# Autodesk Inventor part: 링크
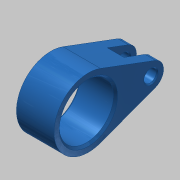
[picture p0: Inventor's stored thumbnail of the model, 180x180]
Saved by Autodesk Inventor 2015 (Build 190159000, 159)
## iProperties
Created: 2016-08
Part Number: 링크
Material: 강철, 탄소
Document SubType Name: Modeling
Designer: mduedu
Density: 7.87 g/cm^3
Appearance: 청록색
Author: mduedu
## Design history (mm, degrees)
sketch "스케치1"
  geometry: L1 (32.1, 5.62)-(5.775, 15.456); L2 (32.1, -5.62)-(5.775, -15.456); C1 r 13 at (0, 0); C2 r 3 at (30, 0); A1 r 16.5 centre (0, 0) between (5.775, 15.456) and (5.775, -15.456); A2 r 6 centre (30, 0) between (32.1, 5.62) and (32.1, -5.62); 1 further point
  constraints: 4 centre point, 4 end point, 4 point on circle, 4 tangent, 3 coincident, 1 horizontal alignment
  dimensions: "d0" = 33 diameter of A1; "d2" = 12 diameter of A2; "d3" = 30 distance of A2.centre point (0, 0); "d4" = 26 diameter of C1; "d5" = 6 diameter of C2
extrude "돌출1" new body sketch "스케치1" stored distance "d6" = 18; taper "d7" = 0 deg
sketch "스케치2"
  geometry: L1 (-9, 36)-(9, 36) reference; L2 (0, 0)-(0, 36); L3 (-4, 36)-(4, 36); L4 (4, 36)-(4, 22); L5 (4, 22)-(-4, 22); L6 (-4, 22)-(-4, 36)
  constraints: 10 end point, 2 midpoint, 2 parallel, 1 horizontal, 1 perpendicular, 1 point on line
  dimensions: "d8" = 8 distance between parallel lines of L4 L6; "d10" = 14 distance of L3.end L4.end
extrude "돌출2" cut sketch "스케치2" stored distance "d11" = 20; taper "d12" = 0 deg
chamfer "모따기1" distance "d13" = 1; stored, may be unused: second distance "d14" = 2, angle "d15" = 45 deg
chamfer "모따기2" distance "d16" = 0.5; stored, may be unused: second distance "d17" = 2, angle "d18" = 45 deg
node "솔리드1"
